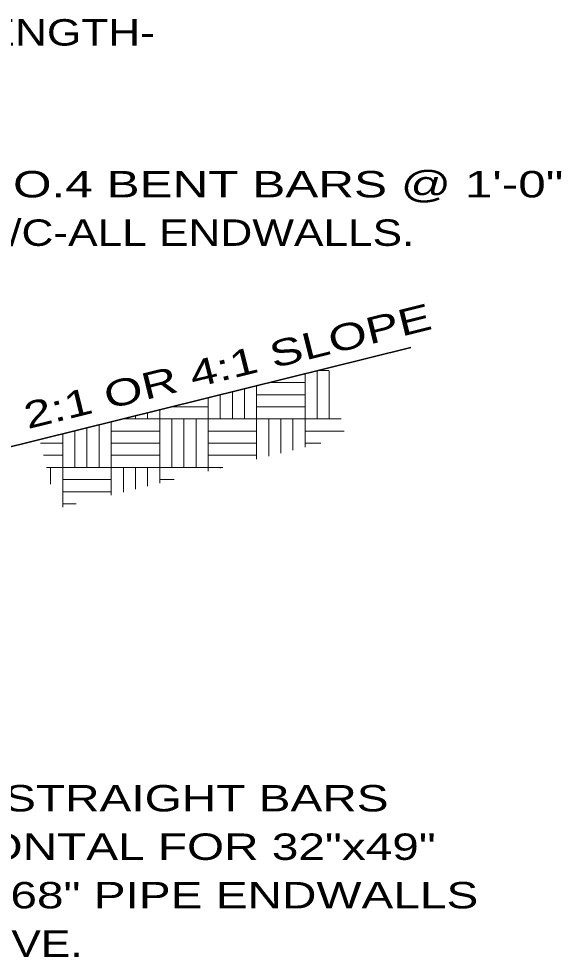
# Model space of a CAD drawing. Extents: x 394.95 to 401.96, y -76.51 to -66.78.
# Drawn here: x 400.612 to 401.844, y -71.363 to -69.233 of the extents above; entities that cross this region are included whole.
import ezdxf
from ezdxf.enums import TextEntityAlignment as Align

# ---------------------------------------------------------------- set-up
doc = ezdxf.new("R2010")
doc.units = 0
doc.header["$LTSCALE"] = 0.024
doc.linetypes.add('LONG_DASHED', pattern=[7.5, 6, -1.5])
doc.layers.add('1', color=7, linetype='LONG_DASHED', lineweight=35)
doc.layers.add('6', color=7, linetype='Continuous', lineweight=13)
doc.layers.add('12', color=7, linetype='Continuous')

msp = doc.modelspace()

# ---------------------------------------------------------------- linework, layer by layer
at = {"layer": '1', "linetype": 'Continuous'}
msp.add_line((400.10335, -70.32509), (401.50187, -69.97902), dxfattribs=at)
at = {"layer": '6'}
for p, q in [((401.26219, -70.14096), (401.26219, -70.03832)), ((401.28969, -70.14096), (401.28969, -70.03152)), ((401.29196, -70.03096), (401.31677, -70.03096)), ((401.31719, -70.14096), (401.31719, -70.03264)), ((401.18083, -70.05846), (401.26219, -70.05846)), ((401.06969, -70.14096), (401.06969, -70.08596)), ((401.09719, -70.14096), (401.09719, -70.07916)), ((401.12469, -70.14096), (401.12469, -70.07235)), ((401.15219, -70.08596), (401.26219, -70.08596)), ((401.04219, -70.14096), (401.04219, -70.09277)), ((400.87719, -70.14096), (400.87719, -70.1336)), ((400.90469, -70.14096), (400.90469, -70.1268)), ((400.95857, -70.11346), (401.04219, -70.11346)), ((401.15219, -70.11346), (401.26219, -70.11346)), ((400.79469, -70.25096), (400.79469, -70.15402)), ((400.82219, -70.25096), (400.82219, -70.14722)), ((400.84969, -70.14096), (400.84969, -70.14041)), ((400.95969, -70.25096), (400.95969, -70.14096)), ((400.98719, -70.25096), (400.98719, -70.14096)), ((401.01469, -70.25096), (401.01469, -70.14096)), ((401.04219, -70.25096), (401.04219, -70.14096)), ((401.17969, -70.22526), (401.17969, -70.14096)), ((401.20719, -70.21845), (401.20719, -70.14096)), ((401.23469, -70.21166), (401.23469, -70.14096)), ((401.26219, -70.20485), (401.26219, -70.14096)), ((401.26219, -70.14096), (401.344, -70.14096)), ((400.71219, -70.25096), (400.71219, -70.17443)), ((400.73969, -70.25096), (400.73969, -70.16763)), ((400.76719, -70.25096), (400.76719, -70.16081)), ((400.82219, -70.16846), (400.93219, -70.16846)), ((401.04219, -70.16846), (401.15219, -70.16846)), ((401.26219, -70.16846), (401.3508, -70.16846)), ((400.66164, -70.19596), (400.71219, -70.19596)), ((400.82219, -70.19596), (400.93219, -70.19596)), ((401.04219, -70.19596), (401.15219, -70.19596)), ((401.26219, -70.19596), (401.29809, -70.19596)), ((400.66844, -70.22346), (400.71219, -70.22346)), ((400.82219, -70.22346), (400.93219, -70.22346)), ((401.04219, -70.22346), (401.15219, -70.22346)), ((400.67524, -70.25096), (400.71219, -70.25096)), ((400.68469, -70.28917), (400.68469, -70.25096)), ((400.71219, -70.34096), (400.71219, -70.25096)), ((400.71219, -70.25096), (400.82219, -70.25096)), ((400.82219, -70.31373), (400.82219, -70.25096)), ((400.82219, -70.25096), (400.93219, -70.25096)), ((400.84969, -70.30693), (400.84969, -70.25096)), ((400.87719, -70.30011), (400.87719, -70.25096)), ((400.90469, -70.29332), (400.90469, -70.25096)), ((400.93219, -70.28651), (400.93219, -70.25096)), ((400.93219, -70.25096), (401.04219, -70.25096)), ((401.04219, -70.25929), (401.04219, -70.25096)), ((401.04219, -70.25096), (401.07584, -70.25096)), ((401.06969, -70.25248), (401.06969, -70.25096)), ((400.71219, -70.27846), (400.82219, -70.27846)), ((400.93219, -70.27846), (400.96472, -70.27846)), ((400.71219, -70.30596), (400.82219, -70.30596)), ((400.71219, -70.33346), (400.74246, -70.33346))]:
    msp.add_line(p, q, dxfattribs=at)
for points in [[(401.15219, -70.23206), (401.15219, -70.14096), (401.15219, -70.06555)], [(400.93219, -70.25096), (400.93219, -70.14096), (400.93219, -70.11999)], [(400.84746, -70.14096), (400.93219, -70.14096), (401.04219, -70.14096)], [(401.04219, -70.14096), (401.15219, -70.14096), (401.26219, -70.14096)]]:
    msp.add_lwpolyline(points, dxfattribs=at)

# ---------------------------------------------------------------- texts
at = {"layer": '12'}
for s, width, p in [('BOTTOM BARS TO BE FULL LENGTH-', 1.25, (399.12139, -69.29361)), ('NO.4 BENT BARS @ 1\'-0"', 1.4, (400.51823, -69.63811)), ('C/C-ALL ENDWALLS.', 1.25, (400.51823, -69.74811)), ('2-NO.4 STRAIGHT BARS ', 1.35, (400.19985, -71.03167)), ('HORIZONTAL FOR 32"x49" ', 1.35, (400.19985, -71.14167)), ('TO 43"x68" PIPE ENDWALLS ', 1.35, (400.19985, -71.25167)), ('INCLUSIVE.', 1.25, (400.19985, -71.36167))]:
    msp.add_text(s, height=0.06, dxfattribs=dict(at, width=width)).set_placement(p)
at = {"layer": '12', "width": 1.4}
msp.add_text('2:1 OR 4:1 SLOPE', height=0.06, rotation=13.899, dxfattribs=at).set_placement((401.0932, -70.05014), align=Align.CENTER)

doc.saveas('drawing.dxf')
